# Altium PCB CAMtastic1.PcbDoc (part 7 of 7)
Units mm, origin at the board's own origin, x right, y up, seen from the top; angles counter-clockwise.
Board outline 150.22 x 135.24 mm, 5 copper layers (Top Layer, Layer 1, Mid-Layer 1, Layer 2, Bottom Layer), stack 0.461 mm thick; 0 components, 362 nets, 2885 pads, 0 vias.
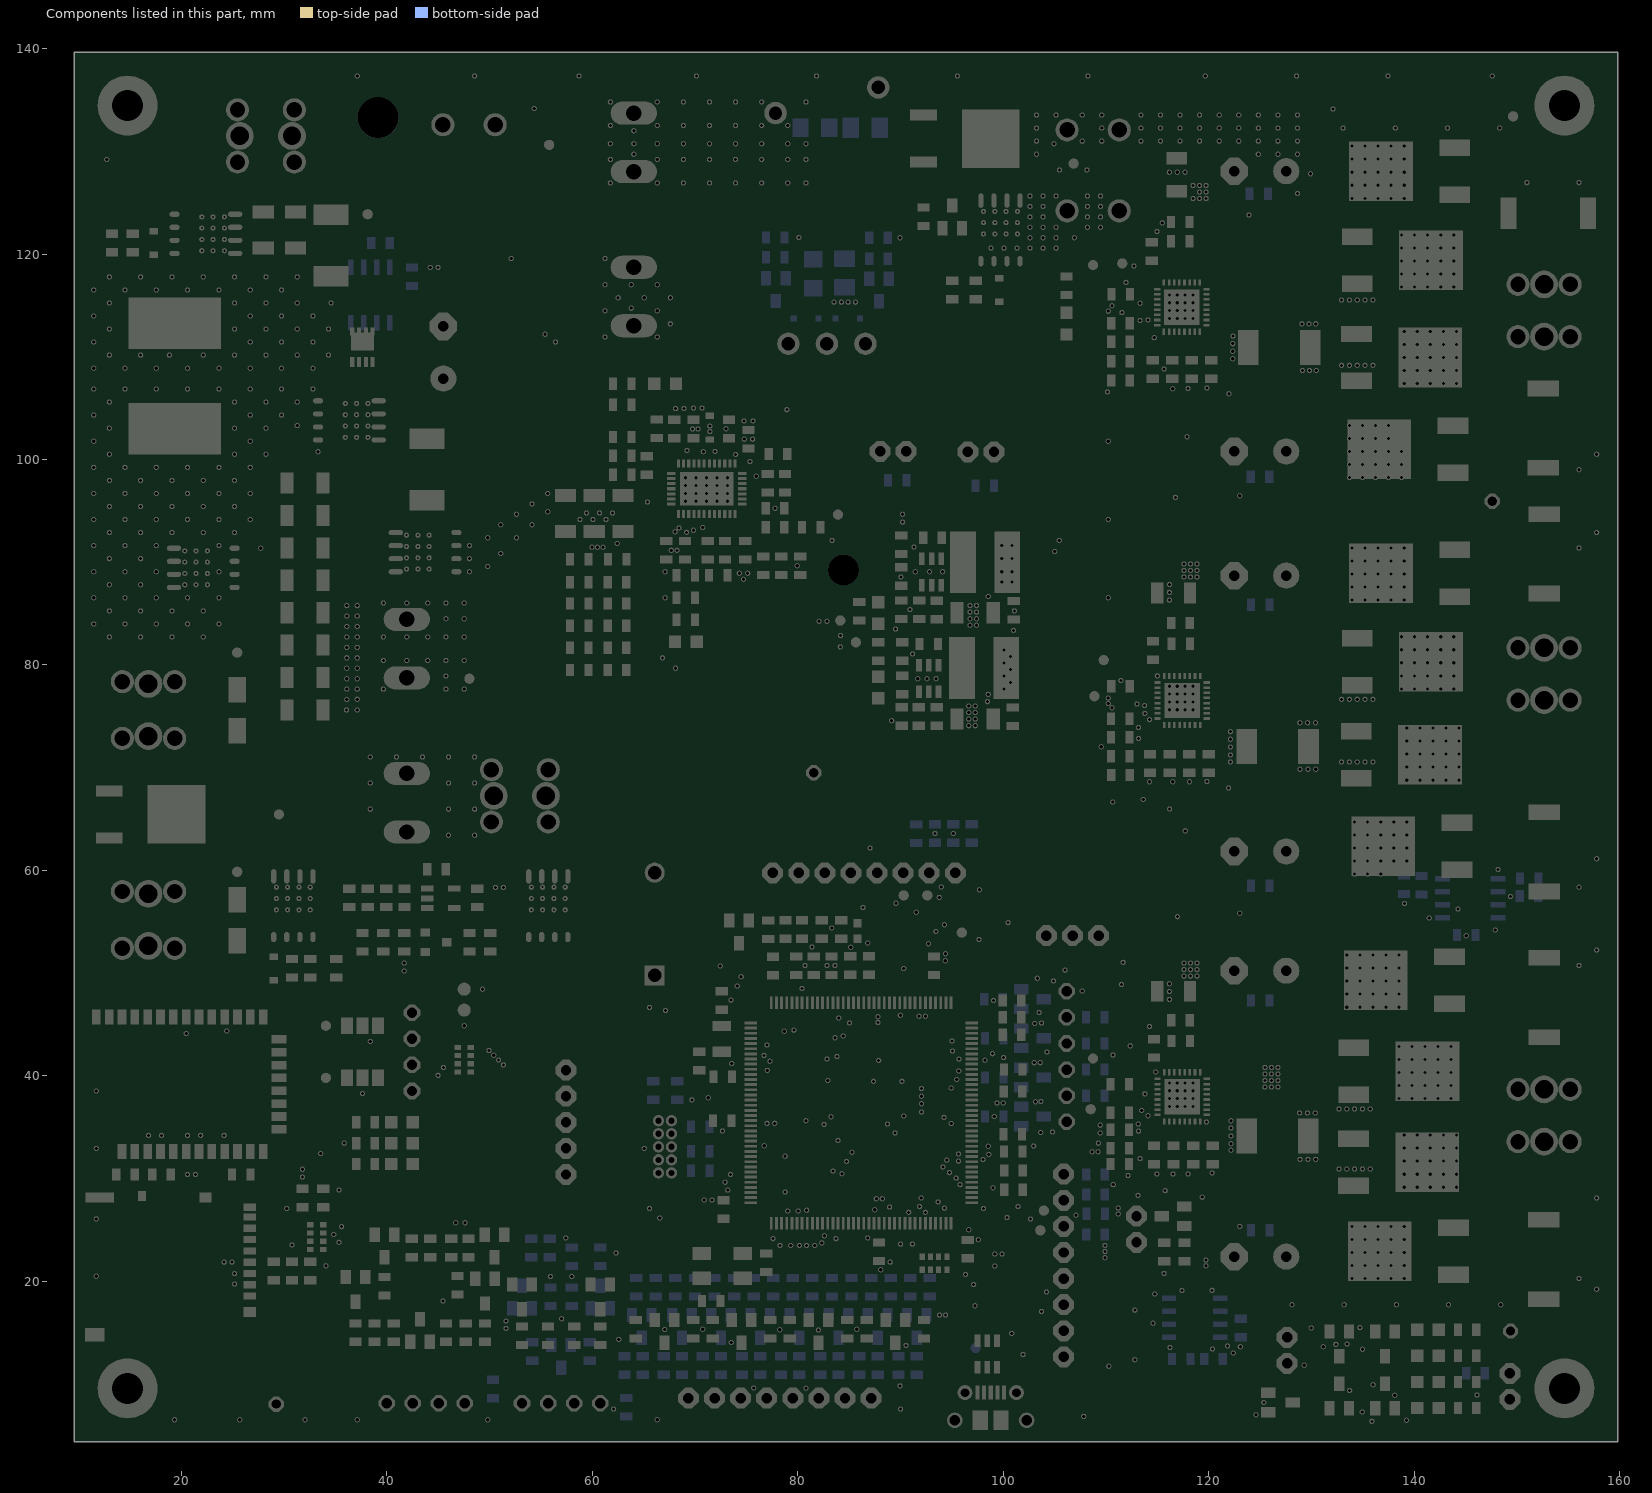
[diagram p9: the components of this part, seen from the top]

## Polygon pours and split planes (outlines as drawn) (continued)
no net on Top Overlay (solid): 158.333,30.354 156.233,30.354 156.233,41.934 158.333,41.934
no net on Top Overlay (solid): 41.657,31.32 41.457,31.32 41.457,31.52 41.657,31.52
no net on Top Overlay (solid): 41.657,33.352 41.457,33.352 41.457,33.552 41.657,33.552
no net on Top Overlay (solid): 41.657,35.384 41.457,35.384 41.457,35.584 41.657,35.584
no net on Top Overlay (solid): 64.31,35.646 64.01,35.446 64.01,35.846
no net on Top Overlay (solid): 114.383,39.706 114.129,39.553 114.129,39.858
no net on Top Overlay (solid): 94.924,48.082 94.67,48.463 95.178,48.463
no net on Top Overlay (solid): 124.746,49.098 124.111,49.098 124.111,51.384 124.746,51.384
no net on Top Overlay (solid): 13.185,49.396 11.085,49.396 11.085,60.976 13.185,60.976
no net on Top Overlay (solid): 28.482,53.368 28.482,53.268 28.081,53.268 28.081,53.668 28.182,53.668
no net on Top Overlay (solid): 53.3,53.368 53.3,53.268 52.9,53.268 52.9,53.668 53,53.668
no net on Top Overlay (solid): 124.746,60.706 124.111,60.706 124.111,62.992 124.746,62.992
no net on Top Overlay (solid): 58.725,61.558 47.145,61.558 47.145,63.658 58.725,63.658
no net on Top Overlay (solid): 126 vertices, not listed, extent 67.447,64.718 67.978,65.526
no net on Top Overlay (solid): 100 vertices, not listed, extent 66.13,64.949 66.638,65.526
no net on Top Overlay (solid): 94 vertices, not listed, extent 68.116,64.949 68.647,65.526
no net on Top Overlay (solid): 72 vertices, not listed, extent 69.732,64.949 69.848,65.734
no net on Top Overlay (solid): 84 vertices, not listed, extent 70.656,64.949 70.979,65.711
no net on Top Overlay (solid): 94 vertices, not listed, extent 71.071,64.949 71.579,65.526
no net on Top Overlay (solid): 95 vertices, not listed, extent 72.826,64.949 73.311,65.526
no net on Top Overlay (solid): 84 vertices, not listed, extent 73.403,64.949 73.727,65.711
no net on Top Overlay (solid): 55 vertices, not listed, extent 73.842,64.949 73.981,65.503
no net on Top Overlay (solid): 77 vertices, not listed, extent 74.142,64.949 74.696,65.526
no net on Top Overlay (solid): 101 vertices, not listed, extent 75.505,64.949 76.013,65.526
no net on Top Overlay (solid): 73 vertices, not listed, extent 76.151,64.949 76.29,65.734
no net on Top Overlay (solid): 94 vertices, not listed, extent 76.428,64.949 76.936,65.526
no net on Top Overlay (solid): 110 vertices, not listed, extent 68.74,64.949 69.248,65.526
no net on Top Overlay (solid): 119 vertices, not listed, extent 66.8,64.949 67.285,65.526
no net on Top Overlay (solid): 127 vertices, not listed, extent 70.033,64.949 70.54,65.526
no net on Top Overlay (solid): 70 vertices, not listed, extent 71.718,64.949 72.064,65.526
no net on Top Overlay (solid): 126 vertices, not listed, extent 72.157,64.949 72.665,65.526
no net on Top Overlay (solid): 122 vertices, not listed, extent 74.858,64.949 75.343,65.526
no net on Top Overlay (solid): 156 vertices, not listed, extent 65.276,64.949 65.992,65.734
no net on Top Overlay (solid): 17 vertices, not listed, extent 73.842,65.618 73.981,65.734
no net on Top Overlay (solid): 753 vertices, not listed, extent 65.946,66.403 76.013,72.407
no net on Top Overlay (solid): 13.185,69.826 11.085,69.826 11.085,81.406 13.185,81.406
no net on Top Overlay (solid): 150 vertices, not listed, extent 76.336,71.829 77.444,72.915
no net on Top Overlay (solid): 605 vertices, not listed, extent 68.786,73.191 73.173,77.601
no net on Top Overlay (solid): 158.333,73.331 156.233,73.331 156.233,84.911 158.333,84.911
no net on Top Overlay (solid): 87.312,77.5 87.162,77.5 87.162,77.8 87.312,77.8
no net on Top Overlay (solid): 87.987,77.5 87.687,77.5 87.687,77.8 87.987,77.8
no net on Top Overlay (solid): 88.512,77.5 88.362,77.5 88.362,77.8 88.512,77.8
no net on Top Overlay (solid): 114.383,78.295 114.129,78.143 114.129,78.447
no net on Top Overlay (solid): 69.092,81.588 68.792,81.588 68.792,81.738 69.092,81.738
no net on Top Overlay (solid): 69.092,82.113 68.792,82.113 68.792,82.413 69.092,82.413
no net on Top Overlay (solid): 69.092,82.788 68.792,82.788 68.792,82.938 69.092,82.938
no net on Top Overlay (solid): 87.312,84.765 87.162,84.765 87.162,85.065 87.312,85.065
no net on Top Overlay (solid): 87.987,84.765 87.687,84.765 87.687,85.065 87.987,85.065
no net on Top Overlay (solid): 88.512,84.765 88.362,84.765 88.362,85.065 88.512,85.065
no net on Top Overlay (solid): 25.417,86.659 25.017,86.659 25.017,86.759 25.317,87.059 25.417,87.059
no net on Top Overlay (solid): 124.746,87.554 124.111,87.554 124.111,89.84 124.746,89.84
no net on Top Overlay (solid): 47.007,88.183 46.606,88.183 46.606,88.283 46.907,88.583 47.007,88.583
no net on Top Overlay (solid): 68.577,93.855 68.177,93.855 68.377,94.055
no net on Top Overlay (solid): 124.746,99.644 124.111,99.644 124.111,101.93 124.746,101.93
no net on Top Overlay (solid): 33.443,106.51 33.143,106.21 33.043,106.21 33.043,106.61 33.443,106.61
no net on Top Overlay (solid): 67.377,106.691 67.077,106.691 67.077,106.841 67.377,106.841
no net on Top Overlay (solid): 67.377,107.216 67.077,107.216 67.077,107.516 67.377,107.516
no net on Top Overlay (solid): 67.377,107.891 67.077,107.891 67.077,108.041 67.377,108.041
no net on Top Overlay (solid): 158.333,108.713 156.233,108.713 156.233,120.293 158.333,120.293
no net on Top Overlay (solid): 46.63,110.668 44.344,110.668 44.344,111.303 46.63,111.303
no net on Top Overlay (solid): 105.626,112.921 105.476,112.921 105.476,113.221 105.626,113.221
no net on Top Overlay (solid): 106.301,112.921 106.001,112.921 106.001,113.221 106.301,113.221
no net on Top Overlay (solid): 106.826,112.921 106.676,112.921 106.676,113.221 106.826,113.221
no net on Top Overlay (solid): 114.357,116.586 114.103,116.434 114.103,116.738
no net on Top Overlay (solid): 97.316,119.154 97.316,119.054 96.915,119.054 96.915,119.454 97.016,119.454
no net on Top Overlay (solid): 19.473,124.671 19.173,124.371 19.073,124.371 19.073,124.771 19.473,124.771
no net on Top Overlay (solid): 124.746,126.924 124.111,126.924 124.111,129.21 124.746,129.21
no net on Top Overlay (solid): 34.005,135.096 22.425,135.096 22.425,137.196 34.005,137.196
$Net6 on Layer 1 "Mid-Layer 2-$Net6" (solid, pour order 2180): 463 vertices, not listed, extent 10.952,5.776 158.417,138.24
$Net109 on Layer 1 "Mid-Layer 2-$Net109" (solid, pour order 1140): 33.295,126.924 28.723,126.924 28.723,136.83 33.295,136.83
$Net4 on Layer 1 "Mid-Layer 2-$Net4" (solid, pour order 1138): 34.311,103.048 34.311,102.794 34.057,102.54 31.263,102.54 29.231,100.508 28.469,99.746 27.707,98.984 27.707,97.206 27.707,92.126 24.151,92.126 24.151,82.728 22.627,81.204 10.952,81.204 10.952,107.366 34.311,107.366
$Net116 on Layer 1 "Mid-Layer 2-$Net116" (solid, pour order 1136): 61.32,91.135 59.669,91.135 59.669,91.796 61.32,91.796
$Net3 on Layer 1 "Mid-Layer 2-$Net3 2" (solid, pour order 1134): 68.093,119.558 68.093,113.462 62.759,108.128 62.759,101.524 35.327,101.524 35.327,106.604 41.423,106.604 44.471,109.652 56.409,109.652 59.965,113.208 59.965,119.558 60.727,120.32 67.331,120.32
$Net110 on Layer 1 "Mid-Layer 2-$Net110" (solid, pour order 1132): 40.661,108.382 10.952,108.382 10.952,119.558 40.661,119.558
$Net100 on Layer 1 "Mid-Layer 2-$Net100" (solid, pour order 2178): 119.282,51.096 119.282,49.488 119.045,49.251 117.564,49.251 117.25,49.564 117.25,51.096 117.513,51.359 119.02,51.359
$Net100 on Layer 1 "Mid-Layer 2-$Net100 1" (solid, pour order 2176): 119.257,89.882 119.257,88.274 119.02,88.036 117.538,88.036 117.225,88.35 117.225,89.882 117.488,90.145 118.994,90.145
$Net100 on Layer 1 "Mid-Layer 2-$Net100 2" (solid, pour order 2174): 120.121,126.737 120.121,125.129 119.883,124.892 118.402,124.892 118.089,125.205 118.089,126.737 118.351,127 119.858,127
$Net156 on Layer 1 "Mid-Layer 2-$Net156" (solid, pour order 2172): 21.357,50.724 12.213,50.724 12.213,54.534 21.357,54.534
$Net157 on Layer 1 "Mid-Layer 2-$Net157" (solid, pour order 2170): 21.357,55.804 12.213,55.804 12.213,60.122 21.357,60.122
$Net80 on Layer 1 "Mid-Layer 2-$Net80" (solid, pour order 2168): 52.599,61.392 34.819,61.392 34.819,69.266 37.105,71.552 52.599,71.552
$Net107 on Layer 1 "Mid-Layer 2-$Net107" (solid, pour order 2162): 137.113,118.747 137.113,106.958 136.404,106.248 129.441,106.248 128.731,106.958 128.731,118.747 129.441,119.456 136.404,119.456
$Net7 on Layer 1 "Mid-Layer 2-$Net7" (solid, pour order 2160): 156.747,35.003 156.747,23.315 155.86,22.428 142.649,22.428 141.939,23.138 141.939,26.948 141.378,27.508 137.823,27.508 137.113,28.218 137.113,34.927 137.823,35.636 156.114,35.636
$Net9 on Layer 1 "Mid-Layer 2-$Net9" (solid, pour order 2158): 18 vertices, not listed, extent 128.223,27.508 136.859,40.716
$Net8 on Layer 1 "Mid-Layer 2-$Net8" (solid, pour order 2156): 149.305,47.184 149.305,46.865 149.866,46.304 155.86,46.304 156.671,45.493 156.671,37.133 155.936,36.398 137.823,36.398 137.113,37.108 137.113,43.817 137.686,44.389 146.13,44.389 146.328,44.429 146.497,44.541 149.188,47.232
$Net10 on Layer 1 "Mid-Layer 2-$Net10" (solid, pour order 2154): 40 vertices, not listed, extent 124.921,19.888 139.907,44.389
$Net102 on Layer 1 "Mid-Layer 2-$Net102" (solid, pour order 2152): 17 vertices, not listed, extent 137.367,62.052 156.849,78.562
$Net101 on Layer 1 "Mid-Layer 2-$Net101" (solid, pour order 2150): 18 vertices, not listed, extent 128.223,67.132 137.113,80.34
$Net103 on Layer 1 "Mid-Layer 2-$Net103" (solid, pour order 2148): 21 vertices, not listed, extent 137.367,76.276 156.824,92.786
$Net10 on Layer 1 "Mid-Layer 2-$Net10 1" (solid, pour order 2146): 80 vertices, not listed, extent 97.362,42.86 139.907,134.366
$Net105 on Layer 1 "Mid-Layer 2-$Net105" (solid, pour order 2144): 156.671,113.641 156.671,102.995 155.86,102.184 138.838,102.184 138.129,102.894 138.129,103.134 138.138,103.155 138.16,103.327 138.138,103.5 138.129,103.52 138.129,113.667 138.838,114.376 155.936,114.376
$Net106 on Layer 1 "Mid-Layer 2-$Net106" (solid, pour order 2142): 32 vertices, not listed, extent 138.155,114.859 156.697,131.75
$Net156 on Layer 1 "Mid-Layer 2-$Net156 1" (solid, pour order 2140): 21.357,70.536 12.213,70.536 12.213,75.108 21.357,75.108
$Net158 on Layer 1 "Mid-Layer 2-$Net158" (solid, pour order 2138): 21.357,76.124 12.213,76.124 12.213,80.696 21.357,80.696
$Net3 on Layer 1 "Mid-Layer 2-$Net3" (solid, pour order 2136): 97.845,85.945 97.845,73.872 97.608,73.635 94.938,73.609 94.848,73.698 94.848,86.208 97.582,86.208
$Net3 on Layer 1 "Mid-Layer 2-$Net3 1" (solid, pour order 2134): 37.867,74.092 32.533,74.092 32.533,86.792 37.867,86.792
$Net2 on Layer 1 "Mid-Layer 2-$Net2" (solid, pour order 2132): 45.741,94.92 44.725,93.904 44.725,88.824 39.899,88.824 39.899,93.396 41.931,95.428 41.931,96.952 45.741,96.952
$Net19 on Layer 1 "Mid-Layer 2-$Net19" (solid, pour order 2130): 42.185,49.708 41.169,49.708 41.169,51.486 42.185,51.486
$Net19 on Layer 1 "Mid-Layer 2-$Net19 1" (solid, pour order 2128): 51.837,57.836 50.059,57.836 50.059,58.852 51.837,58.852
$Net19 on Layer 1 "Mid-Layer 2-$Net19 2" (solid, pour order 2126): 86.11,114.91 83.079,114.91 83.079,116.18 86.11,116.18
$Net117 on Layer 1 "Mid-Layer 2-$Net117" (solid, pour order 2124): 81.301,126.416 61.235,126.416 61.235,135.306 81.301,135.306
$Net160 on Layer 1 "Mid-Layer 2-$Net160" (solid, pour order 2122): 27.707,126.924 23.135,126.924 23.135,136.83 27.707,136.83
$Net0 on Layer 2 "Mid-Layer 1-$Net0" (solid, pour order 1130): 80 vertices, not listed, extent 10.952,5.776 158.417,138.24
$Net111 on Layer 2 "Mid-Layer 1-$Net111" (solid, pour order 1106): 64.283,95.682 57.171,95.682 49.043,87.554 49.043,77.14 39.137,77.14 39.137,87.808 44.217,87.808 45.995,89.586 45.995,92.126 48.789,92.126 53.869,97.206 64.283,97.206
$Net2 on Layer 2 "Mid-Layer 1-$Net2" (solid, pour order 1104): 45.741,94.92 44.725,93.904 44.725,88.824 39.899,88.824 39.899,93.396 41.931,95.428 41.931,96.952 45.741,96.952
$Net107 on Layer 2 "Mid-Layer 1-$Net107" (solid, pour order 1102): 137.113,118.747 137.113,106.958 136.404,106.248 129.441,106.248 128.731,106.958 128.731,118.747 129.441,119.456 136.404,119.456
$Net10 on Layer 2 "Mid-Layer 1-$Net10" (solid, pour order 1100): 130.255,132.615 130.255,125.754 129.622,125.12 124.767,125.12 124.235,125.652 124.235,129.36 123.827,129.769 104.298,129.769 102.749,128.219 97.159,128.219 97.159,134.366 128.504,134.366
$Net117 on Layer 2 "Mid-Layer 1-$Net117" (solid, pour order 1098): 81.301,126.416 61.235,126.416 61.235,135.306 81.301,135.306
$Net160 on Layer 2 "Mid-Layer 1-$Net160" (solid, pour order 1096): 27.707,126.924 23.135,126.924 23.135,136.83 27.707,136.83
$Net109 on Layer 2 "Mid-Layer 1-$Net109" (solid, pour order 1094): 33.295,126.924 28.723,126.924 28.723,136.83 33.295,136.83
$Net105 on Layer 2 "Mid-Layer 1-$Net105" (solid, pour order 1092): 156.671,113.641 156.671,102.995 155.86,102.184 138.838,102.184 138.129,102.894 138.129,103.134 138.138,103.155 138.16,103.327 138.138,103.5 138.129,103.52 138.129,113.667 138.838,114.376 155.936,114.376
$Net106 on Layer 2 "Mid-Layer 1-$Net106" (solid, pour order 4): 32 vertices, not listed, extent 138.155,114.859 156.697,131.75
$Net4 on Layer 2 "Mid-Layer 1-$Net4" (solid, pour order 2): 17 vertices, not listed, extent 10.952,81.204 34.311,107.366
$Net110 on Layer 2 "Mid-Layer 1-$Net110" (solid, pour order 0): 40.661,108.382 10.952,108.382 10.952,119.558 40.661,119.558
$Net7 on Layer 2 "Mid-Layer 1-$Net7" (solid, pour order 1128): 156.747,35.003 156.747,23.315 155.86,22.428 142.649,22.428 141.939,23.138 141.939,26.948 141.378,27.508 137.823,27.508 137.113,28.218 137.113,34.927 137.823,35.636 156.114,35.636
$Net9 on Layer 2 "Mid-Layer 1-$Net9" (solid, pour order 1126): 18 vertices, not listed, extent 128.223,27.508 136.859,40.716
$Net8 on Layer 2 "Mid-Layer 1-$Net8" (solid, pour order 1124): 24 vertices, not listed, extent 137.113,36.398 156.671,53.162
$Net156 on Layer 2 "Mid-Layer 1-$Net156" (solid, pour order 1122): 21.357,50.724 12.213,50.724 12.213,54.534 21.357,54.534
$Net157 on Layer 2 "Mid-Layer 1-$Net157" (solid, pour order 1120): 21.357,55.804 12.213,55.804 12.213,60.122 21.357,60.122
$Net80 on Layer 2 "Mid-Layer 1-$Net80" (solid, pour order 1118): 52.599,61.392 35.581,61.392 35.581,70.028 37.105,71.552 52.599,71.552
$Net156 on Layer 2 "Mid-Layer 1-$Net156 1" (solid, pour order 1116): 21.357,70.536 12.213,70.536 12.213,75.108 21.357,75.108
$Net158 on Layer 2 "Mid-Layer 1-$Net158" (solid, pour order 1114): 21.357,76.124 12.213,76.124 12.213,80.696 21.357,80.696
$Net102 on Layer 2 "Mid-Layer 1-$Net102" (solid, pour order 1112): 17 vertices, not listed, extent 137.367,62.052 156.849,78.562
$Net101 on Layer 2 "Mid-Layer 1-$Net101" (solid, pour order 1110): 18 vertices, not listed, extent 128.223,67.132 137.113,80.34
$Net103 on Layer 2 "Mid-Layer 1-$Net103" (solid, pour order 1108): 21 vertices, not listed, extent 137.367,76.276 156.824,92.786

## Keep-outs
Keep-Out Layer:
  the board outline again, w0.254

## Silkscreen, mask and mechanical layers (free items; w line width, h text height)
Top Overlay:
  drawing of 12804 lines, arcs and shapes, not listed
Bottom Overlay:
  drawing of 2897 lines, arcs and shapes, not listed
Mechanical 5:
  lines w0: 10.435,5.258 158.935,5.258 158.935,138.758 10.435,138.758 10.435,5.258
